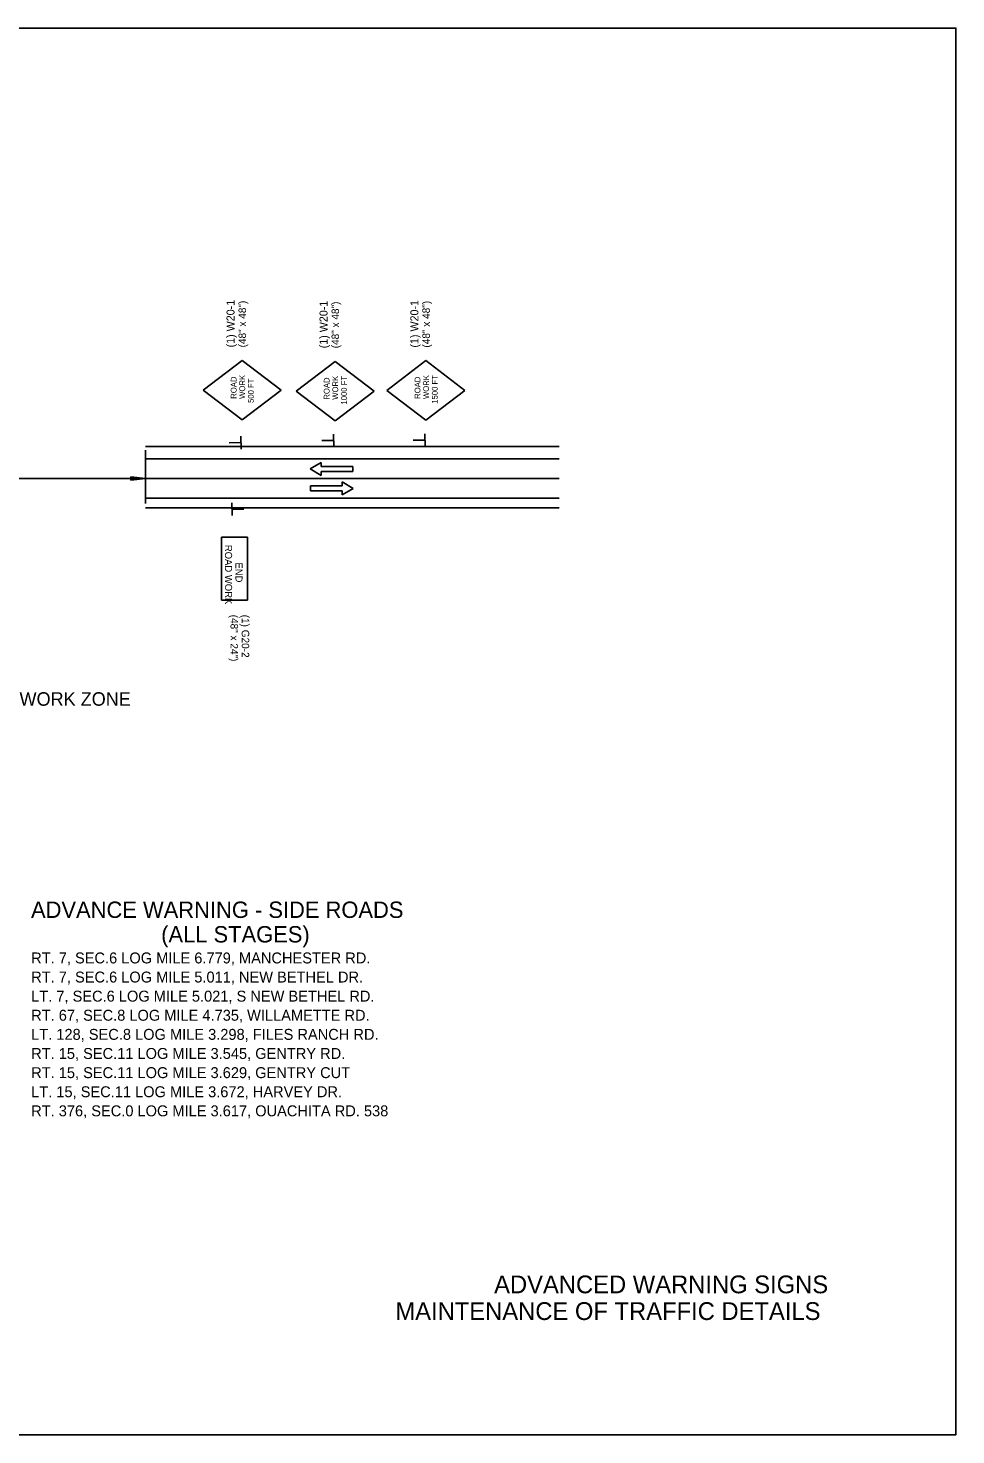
# Model space of a CAD drawing. Extents: x 1416408 to 1429341, y 372694 to 383211.
# Drawn here: x 1417967 to 1419128, y 376066 to 377826 of the extents above; entities that cross this region are included whole.
import ezdxf

# ---------------------------------------------------------------- set-up
doc = ezdxf.new("R2010")
doc.units = 0
for name, color, linetype in [('Default', 7, 'Continuous'), ('DSN_DRFT_Junk-No-Plot', 7, 'Continuous'), ('R_Border Notes', 7, 'Continuous'), ('R_Draft', 7, 'Continuous'), ('R_Exist Surface', 7, 'Continuous'), ('R_MOT', 7, 'Continuous')]:
    doc.layers.add(name, color=color, linetype=linetype)

msp = doc.modelspace()

# ---------------------------------------------------------------- linework, layer by layer
at = {"layer": 'Default'}
for p, q in [((1418113.3, 377231.7), (1418113.3, 377298.6)), ((1418319.5, 377275), (1418333.5, 377283.1)), ((1418333.5, 377266.8), (1418319.5, 377275)), ((1418333.5, 377278), (1418333.5, 377283.1)), ((1418333.5, 377278), (1418373, 377278)), ((1418373, 377271.9), (1418373, 377278)), ((1417651, 377262.9), (1418113.3, 377262.9)), ((1417751.4, 377262.9), (1418012.8, 377262.9)), ((1418333.5, 377271.9), (1418373, 377271.9)), ((1418333.5, 377266.8), (1418333.5, 377271.9)), ((1418359.4, 377258.8), (1418359.4, 377253.7)), ((1418359.4, 377258.8), (1418373.3, 377250.6)), ((1418359.4, 377253.7), (1418319.8, 377253.7)), ((1418319.8, 377253.7), (1418319.8, 377247.6)), ((1418359.4, 377247.6), (1418319.8, 377247.6)), ((1418373.3, 377250.6), (1418359.4, 377242.5)), ((1418359.4, 377247.6), (1418359.4, 377242.5))]:
    msp.add_line(p, q, dxfattribs=at)
msp.add_lwpolyline([(1416407.7, 377826.5), (1416407.7, 376066.5), (1419127.7, 376066.5), (1419127.7, 377826.5)], close=True, dxfattribs=at)
at = {"layer": 'DSN_DRFT_Junk-No-Plot'}
msp.add_lwpolyline([(1416407.7, 377826.5), (1419127.7, 377826.5), (1419127.7, 376066.5), (1416407.7, 376066.5)], close=True, dxfattribs=at)
at = {"layer": 'R_Draft'}
for p, q in [((1418095.3, 377264.9), (1418113.3, 377262.9)), ((1418095.3, 377264.9), (1418095.3, 377260.8)), ((1418095.3, 377264.6), (1418110.3, 377262.9)), ((1418095.3, 377264.2), (1418107.2, 377262.9)), ((1418095.3, 377263.9), (1418104.2, 377262.9)), ((1418095.3, 377263.5), (1418101.2, 377262.9)), ((1418095.3, 377263.2), (1418098.2, 377262.9)), ((1418095.3, 377260.8), (1418113.3, 377262.9)), ((1418095.3, 377262.2), (1418101.2, 377262.9)), ((1418095.3, 377261.5), (1418107.2, 377262.9)), ((1418095.3, 377261.2), (1418110.3, 377262.9)), ((1418095.3, 377261.9), (1418104.2, 377262.9)), ((1418095.3, 377262.6), (1418098.2, 377262.9))]:
    msp.add_line(p, q, dxfattribs=at)
at = {"layer": 'R_Exist Surface'}
for p, q in [((1418113.3, 377303.1), (1418631.3, 377303.1)), ((1418113.3, 377287.4), (1418631.3, 377287.4)), ((1418113.3, 377262.9), (1418631.3, 377262.9)), ((1418113.3, 377238.3), (1418631.3, 377238.3)), ((1418113.3, 377226.1), (1418631.3, 377226.1))]:
    msp.add_line(p, q, dxfattribs=at)
at = {"layer": 'R_MOT'}
for p, q in [((1418234.4, 377410.6), (1418185.5, 377373.4)), ((1418234.4, 377410.6), (1418283.3, 377373.4)), ((1418350.8, 377409.5), (1418301.9, 377372.3)), ((1418350.8, 377409.5), (1418399.7, 377372.3)), ((1418464.4, 377410.5), (1418415.5, 377373.3)), ((1418464.4, 377410.5), (1418513.3, 377373.3)), ((1418185.5, 377373.4), (1418234.4, 377336.2)), ((1418283.3, 377373.4), (1418234.4, 377336.2)), ((1418301.9, 377372.3), (1418350.8, 377335.2)), ((1418399.7, 377372.3), (1418350.8, 377335.2)), ((1418415.5, 377373.3), (1418464.4, 377336.1)), ((1418513.3, 377373.3), (1418464.4, 377336.1)), ((1418232.7, 377316), (1418233.1, 377299.9)), ((1418348.6, 377310.5), (1418334.2, 377310.4)), ((1418348.8, 377318.5), (1418349.1, 377302.5)), ((1418462.8, 377310.9), (1418448.4, 377310.8)), ((1418462.9, 377318.9), (1418463.3, 377302.9)), ((1418232.6, 377308), (1418218.2, 377307.8)), ((1418221.8, 377216.6), (1418221.7, 377232.7)), ((1418222, 377224.6), (1418236.4, 377224.6)), ((1418208.4, 377110.6), (1418208.4, 377189.6)), ((1418208.4, 377189.6), (1418241, 377189.6)), ((1418241, 377110.6), (1418241, 377189.6)), ((1418208.4, 377110.6), (1418241, 377110.6))]:
    msp.add_line(p, q, dxfattribs=at)

# ---------------------------------------------------------------- texts
at = {"layer": 'Default'}
msp.add_text('ADVANCE WARNING SIGNS AT BEGINNING AND END OF WORK ZONE', height=16.891, dxfattribs=at).set_placement((1417334.6, 376978.7))
at = {"layer": 'R_Border Notes'}
for s, p in [('ADVANCED WARNING SIGNS', (1418549.8, 376243.6)), ('MAINTENANCE OF TRAFFIC DETAILS', (1418426.2, 376210.2))]:
    msp.add_text(s, height=22.239, dxfattribs=at).set_placement(p)
at = {"layer": 'R_Draft'}
for s, height, p in [('ADVANCE WARNING - SIDE ROADS', 20.502, (1417970.2, 376713.2)), ('(ALL STAGES)', 20.502, (1418133.1, 376682.5)), ('RT. 7, SEC.6 LOG MILE 6.779, MANCHESTER RD.', 13.668, (1417970.4, 376656.3)), ('RT. 7, SEC.6 LOG MILE 5.011, NEW BETHEL DR.', 13.668, (1417970.4, 376632.4)), ('LT. 7, SEC.6 LOG MILE 5.021, S NEW BETHEL RD.', 13.668, (1417970.4, 376608.5)), ('RT. 67, SEC.8 LOG MILE 4.735, WILLAMETTE RD. ', 13.668, (1417970.4, 376584.6)), ('LT. 128, SEC.8 LOG MILE 3.298, FILES RANCH RD.', 13.668, (1417970.4, 376560.7)), ('RT. 15, SEC.11 LOG MILE 3.545, GENTRY RD.', 13.668, (1417970.4, 376536.8)), ('RT. 15, SEC.11 LOG MILE 3.629, GENTRY CUT', 13.668, (1417970.4, 376512.8)), ('LT. 15, SEC.11 LOG MILE 3.672, HARVEY DR.', 13.668, (1417970.4, 376488.9)), ('RT. 376, SEC.0 LOG MILE 3.617, OUACHITA RD. 538', 13.668, (1417970.4, 376465))]:
    msp.add_text(s, height=height, dxfattribs=at).set_placement(p)
at = {"layer": 'R_MOT'}
for s, height, rotation, p in [('(1) W20-1', 10.01, 90, (1418224.9, 377427)), ('(1) W20-1', 10.01, 90, (1418455, 377426.8)), ('(48" x 48")', 9.387, 90, (1418239.3, 377427)), ('(1) W20-1', 10.01, 90, (1418341.3, 377425.9)), ('(48" x 48")', 9.387, 90, (1418355.7, 377425.9)), ('(48" x 48")', 9.387, 90, (1418469.4, 377426.8)), ('ROAD', 7.21, 90.0006, (1418227.4, 377362.7)), ('WORK', 7.21, 90, (1418238.2, 377362.6)), (' 500 FT', 7.21, 90.0007, (1418249, 377354.8)), ('ROAD', 7.21, 90.0006, (1418343.8, 377361.6)), ('WORK', 7.21, 90, (1418354.6, 377361.5)), ('1000 FT', 7.21, 90.0007, (1418365.5, 377355.4)), ('ROAD', 7.21, 90.0006, (1418457.5, 377362.6)), ('WORK', 7.21, 90, (1418468.3, 377362.4)), ('1500 FT', 7.21, 90.0007, (1418479.1, 377356.5)), ('ROAD WORK', 8.87, 270, (1418213, 377180)), ('END', 8.87, 270, (1418226.1, 377158)), ('(48" x 24")', 9.387, 270, (1418219.9, 377092.6)), ('(1) G20-2', 9.39, 270, (1418233.9, 377092.6))]:
    msp.add_text(s, height=height, rotation=rotation, dxfattribs=at).set_placement(p)

doc.saveas('drawing.dxf')
